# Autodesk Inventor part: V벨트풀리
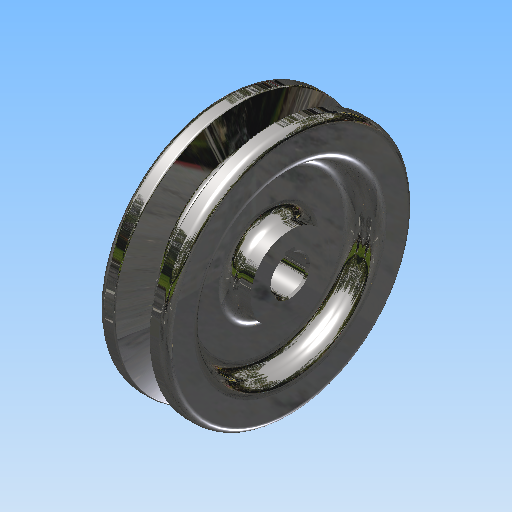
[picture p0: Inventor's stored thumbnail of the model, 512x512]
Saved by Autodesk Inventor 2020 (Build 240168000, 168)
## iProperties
Created: 2015-11
Part Number: V벨트풀리
Material: 강철, 탄소
Document SubType Name: Modeling
Designer: mduedu
Density: 1 g/cm^3
Appearance: 반광택
Author: mduedu
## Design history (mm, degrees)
sketch "스케치1"
  geometry: L1 (-9.5, 0)-(9.5, 0); L2 (0, 0)-(0, 34.7); L3 (-4.825, 34.7)-(-9.5, 34.7); L4 (-9.5, 34.7)-(-9.5, 0); L5 (0, 25.7)-(-2.074, 25.7); L6 (-2.074, 25.7)-(-4.825, 34.7); L7 (4.825, 34.7)-(9.5, 34.7); L8 (9.5, 34.7)-(9.5, 0); L9 (0, 25.7)-(2.074, 25.7); L10 (2.074, 25.7)-(4.825, 34.7); L11 (-9.5, 32)-(9.5, 32); 3 further points
  constraints: 22 end point, 7 point on line, 4 perpendicular, 3 symmetric about line, 1 coincident, 1 horizontal, 1 horizontal alignment, 1 midpoint, 1 vertical
  dimensions: "d0" = 19 distance of L1.start L1.end; "d2" = 69.4 diameter of L2.end L1 (derived); "d3" = 34 deg angle of L10 L6; "d4" = 6.3 distance between parallel lines of L11 L9; "d5" = 2.7 distance between parallel lines of L7 L11; "d6" = 8 distance of point (4, 32) point (-4, 32); "d7" = 64 diameter of L11 L1
revolve "회전1" sketch "스케치1" stored, may be unused: angle "d8" = 90 deg
sketch "스케치2"
  geometry: C1 r 24 at (0, 0); C2 r 11 at (0, 0); 1 further point
  constraints: 2 centre point, 2 coincident
  dimensions: "d9" = 48 diameter of C1; "d10" = 22 diameter of C2
extrude "돌출1" cut sketch "스케치2" distance "d11" = 6; taper "d12" = 0 deg
fillet "모깎기1" dims "d13" = 3
fillet "모깎기2" dims "d14" = 3
fillet "모깎기3" dims "d15" = 1, "d16" = 0.5, "d17" = 2
hole "구멍1" diameter "d20" = 10; stored, may be unused: countersink angle "d24" = 90 deg, drill point angle "d26" = 118 deg; dims "d18" = 10, "d19" = 10, "d21" = 6, "d22" = 4, "d23" = 2, "d25" = 8
sketch "스케치3"
  geometry: L1 (-1.5, 0)-(1.5, 0); L2 (1.5, 0)-(1.5, 6.4); L3 (1.5, 6.4)-(-1.5, 6.4); L4 (-1.5, 6.4)-(-1.5, 0); 2 further points
  constraints: 8 end point, 2 parallel, 1 coincident, 1 horizontal, 1 midpoint, 1 perpendicular
  dimensions: "d27" = 3 distance of L2.end L3.end; "d29" = 6.4 distance of L3.end L1.start
extrude "돌출2" cut sketch "스케치3" extent not by distance; stored distance "d30" = 6; taper "d31" = 0 deg
chamfer "모따기1" distance "d32" = 0.5; stored, may be unused: second distance "d33" = 2, angle "d34" = 45 deg
node "솔리드1"
mirror "대칭1"
